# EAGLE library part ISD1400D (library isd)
VOICE RECORDER
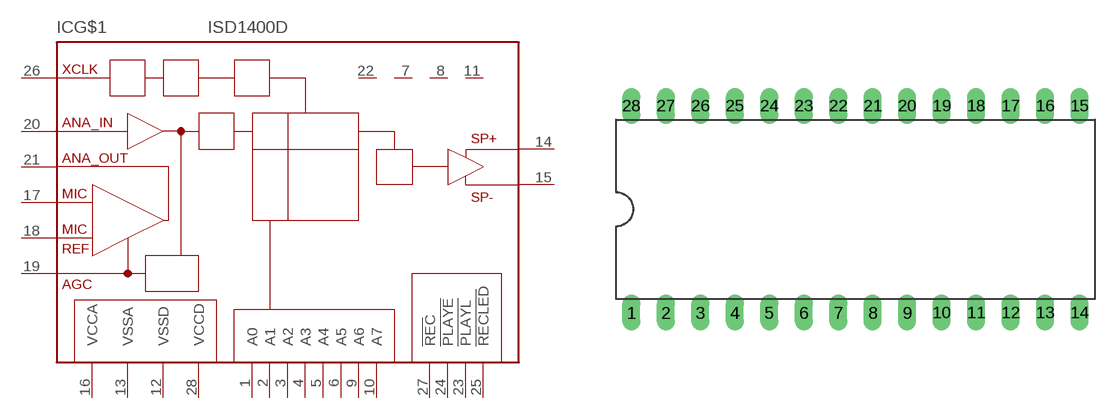
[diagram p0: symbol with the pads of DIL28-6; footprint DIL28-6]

Designator prefix IC; gates G$1=ISD1400 G$2=NC G$3=NC G$4=NC G$5=NC

## ISD1400D (OC_FARNELL: unknown; OC_NEWARK: unknown)  [DIL28-6]
1  G$1:A0  out
2  G$1:A1  out
3  G$1:A2  out
4  G$1:A3  out
5  G$1:A4  out
6  G$1:A5  out
7  G$2:NC  nc
8  G$3:NC  nc
9  G$1:A6  out
10  G$1:A7  out
11  G$4:NC  nc
12  G$1:VSSD  pwr
13  G$1:VSSA  pwr
14  G$1:SP+  out
15  G$1:SP-  out
16  G$1:VCCA  pwr
17  G$1:MIC  in
18  G$1:MIC_REF  in
19  G$1:AGC  pas
20  G$1:ANA_IN  in
21  G$1:ANA_OUT  out
22  G$5:NC  nc
23  G$1:PLAYL  in
24  G$1:PLAYE  in
25  G$1:RECLED  out
26  G$1:XCLK  in
27  G$1:REC  in
28  G$1:VCCD  pwr

## Footprint DIL28-6 (pad centres in mm)
Dual In Line Package 0.6 inch
drill 0.813 long: 1 -16.51,-7.62; 2 -13.97,-7.62; 3 -11.43,-7.62; 4 -8.89,-7.62; 5 -6.35,-7.62; 6 -3.81,-7.62; 7 -1.27,-7.62; 8 1.27,-7.62; 9 3.81,-7.62; 10 6.35,-7.62; 11 8.89,-7.62; 12 11.43,-7.62; 13 13.97,-7.62; 14 16.51,-7.62; 15 16.51,7.62; 16 13.97,7.62; 17 11.43,7.62; 18 8.89,7.62; 19 6.35,7.62; 20 3.81,7.62; 21 1.27,7.62; 22 -1.27,7.62; 23 -3.81,7.62; 24 -6.35,7.62; 25 -8.89,7.62; 26 -11.43,7.62; 27 -13.97,7.62; 28 -16.51,7.62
